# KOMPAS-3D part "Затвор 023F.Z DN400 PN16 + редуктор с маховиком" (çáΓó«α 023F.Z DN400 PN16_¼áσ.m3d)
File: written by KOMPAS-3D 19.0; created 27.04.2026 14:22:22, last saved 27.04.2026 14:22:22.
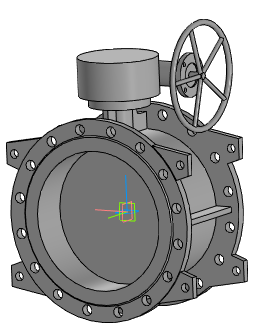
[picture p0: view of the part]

Document properties: Полное имя файла: ..\..\Затвор 023F.Z DN200-DN1600_с маховиком\Затвор 023F.Z DN400 PN16 + редуктор с маховиком.a3d

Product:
- Part/product: Затвор 023F.Z DN400 PN16 + редуктор с маховиком
    Масса: 200.119

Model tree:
1. Операция без истории:1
